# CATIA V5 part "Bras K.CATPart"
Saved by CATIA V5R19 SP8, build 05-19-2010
Part number: Bras K
Revision: ANY
Definition: UNKNOWN
Nomenclature: Bras K
Source: Unknown
Material "Acier": density 7860 kg/m3, Young's modulus 2e+11 Pa, Poisson ratio 0.266, thermal expansion 1.17e-05 1/K
Bounding box of the stored display mesh (mm): x -250 to 5, y -7.491 to 21.5, z 0 to 2.5
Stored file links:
  D:\Documents\1_Travail\1 - ac-limoges.fr\OneDrive - ac-limoges.fr\STI2D_Turgot\2 -2I2D\3_SEQUENCE_Serre_Connectée\3- Spécificités\ITEC\EC 3 Ouverture automatique\Simulation  Ouverture Automatique\Bras K.CATPart
  D:\Documents\1_Travail\1 - ac-limoges.fr\OneDrive - ac-limoges.fr\STI2D_Turgot\2 -2I2D\3_SEQUENCE_Serre_Connectée\Dossier technique_SERRE\Maquettes_CATIA\Simulation statique Ouverture automatique\0-Simu_Statique_Ouverture automatique .CATProduct
  D:\Documents\1_Travail\1 - ac-limoges.fr\OneDrive - ac-limoges.fr\STI2D_Turgot\2 -2I2D\3_SEQUENCE_Serre_Connectée\3- Spécificités\ITEC\EC 3 Ouverture automatique\Simulation  Ouverture Automatique\Corps_de_verin.CATPart
  C:\Program Files\Dassault Systemes\B19\win_b64\startup\materials\French\Catalog.CATMaterial
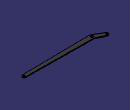
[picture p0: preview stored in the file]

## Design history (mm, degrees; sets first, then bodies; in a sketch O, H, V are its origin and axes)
AxisSystem1 "Système d'axes pour  Cmax": origin (-215, 0, 1.25), X (-0.7917, -0.6109, -0.0007), Y (0.0033, -0.0053, 1), Z (-0.6109, 0.7917, 0.0062)
AxisSystem2 "Système d'axes pour Bmax": origin (0, 0, 1.25), X (-0.7106, -0.7036, 0), Y (0, 0, 1), Z (-0.7036, 0.7106, 0)
Set1
  DatumCurve1: linked copy from another document
Set2
  Point1: type Between, FirstPoint {point type Center, Curve edge [face of Solid1 | face of Solid1]}, SecondPoint {point type Center, Curve edge [face of Solid1 | face of Solid1]}, Ratio 0.5
  Point2: type Between, FirstPoint {point type Center, Curve edge [face of Solid1 | face of Solid1]}, SecondPoint {point type Center, Curve edge [face of Solid1 | face of Solid1]}, Ratio 0.5
Body1 "NONE" (main body), material "Acier"
  Solid1: solid without history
